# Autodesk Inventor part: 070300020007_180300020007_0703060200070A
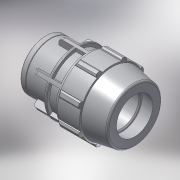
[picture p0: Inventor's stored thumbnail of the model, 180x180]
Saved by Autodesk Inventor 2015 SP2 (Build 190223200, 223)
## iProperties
Created: 2017-02
Part Number: 070300020007_180300020007_0703060200070A
Material: PVC-Piping
Description: PLASSON FEMALE ADAPTOR 20-3/4"
Document SubType Name: Modeling
Designer: KIM
Mass: 92.6774 g
Surface Area: 199.44 cm^2
Volume: 66.1981 cm^3
Density: 1.4 g/cm^3
Appearance: Smooth - White
Author: KIM
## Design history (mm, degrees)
derived "07030.ipt"
feature "Solid1::07030.ipt"
tag "TaggingFeature1"
body "Solid1"
other parameters: "d4" = 11.71429, "d5" = 20.5, "d7" = 48, "d9" = 11.71429, "d11" = 2.34286, "d12" = 38.4, "d13" = 120 deg, "d15" = 12 deg, "d16" = 43.2, "d18" = 1, "d19" = 35 deg, "d20" = 17.5 deg, "d21" = 44.64, "d23" = 0, "d25" = 360 deg, "d27" = 0.96, "d34" = 2.4, "d35" = 24.6, "d36" = 0, "d42" = 20.5, "d43" = 1.44, "d46" = 0.6, "d51" = 82, "d53" = 0.4, "d55" = 360 deg, "d61" = 19, "d62" = 16, "d63" = 24.117, "d64" = 27.33333, "d65" = 2.4, "d66" = 0.5, "d67" = 1, "d68" = 5.7, "d69" = 34.56, "d70" = 1.2, "E_" = 48, "H_" = 82, "l_2" = 19, "Rp_" = 24.117
